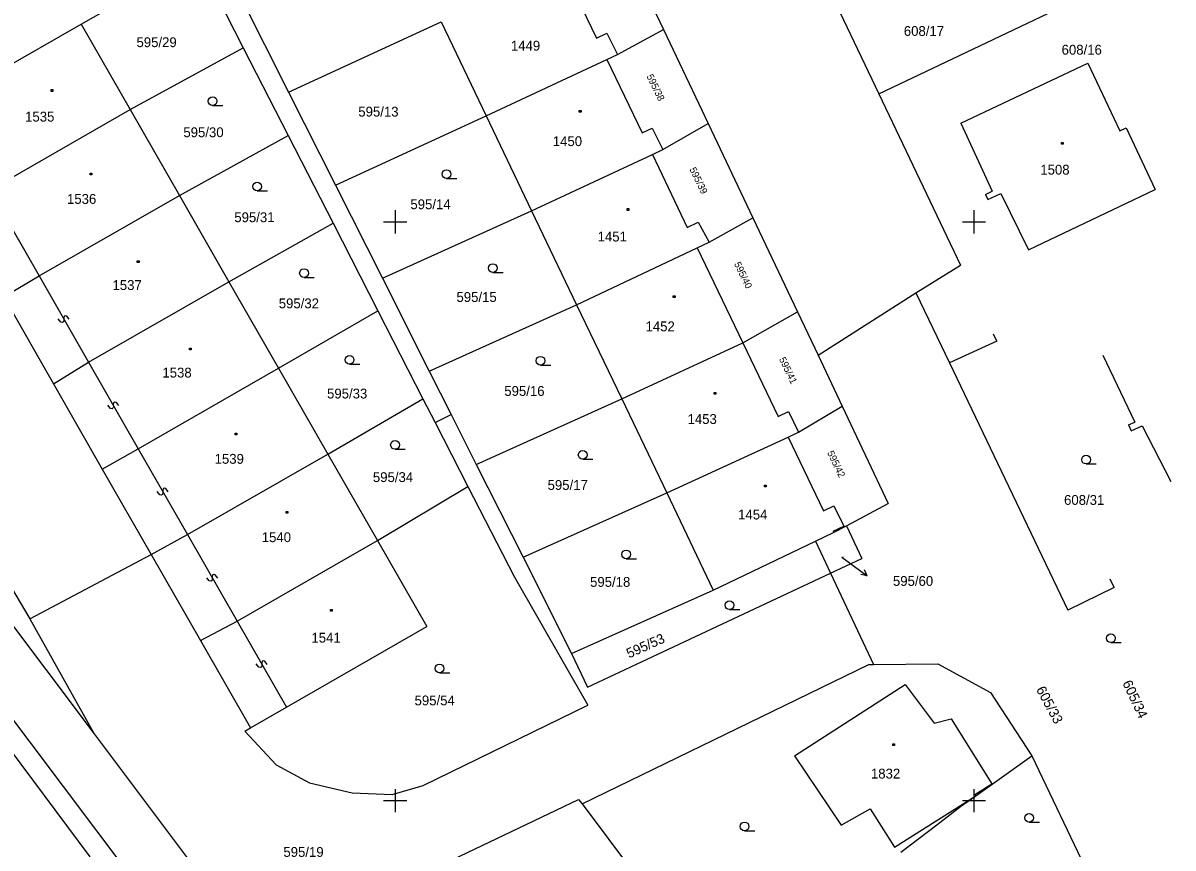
# Model space of a CAD drawing. Extents: x -493648 to -493033, y -1127718 to -1127026.
# Drawn here: x -493132.1 to -493032.8, y -1127404.1 to -1127332.8 of the extents above; entities that cross this region are included whole.
import ezdxf

# ---------------------------------------------------------------- set-up
doc = ezdxf.new("R2010")
doc.units = 0
doc.layers.add('katastrální mapa', color=7, linetype='Continuous')
doc.layers.add('síť', color=7, linetype='Continuous')

msp = doc.modelspace()

# ---------------------------------------------------------------- linework, layer by layer
at = {"layer": 'katastrální mapa'}
for p, q in [((-493068.15, -1127318.07), (-493058.21, -1127338.94)), ((-493080.67, -1127325.26), (-493076.81, -1127333.39)), ((-493127.12, -1127332.93), (-493117.09, -1127327.19)), ((-493117.09, -1127327.19), (-493113.12, -1127334.96)), ((-493085.59, -1127327.9), (-493082.6, -1127334.13)), ((-493058.21, -1127338.94), (-493036.63, -1127328.66)), ((-493113.39, -1127330.48), (-493109.2, -1127338.8)), ((-493139.25, -1127339.87), (-493127.12, -1127332.93)), ((-493127.12, -1127332.93), (-493122.88, -1127340.31)), ((-493109.2, -1127338.8), (-493096.02, -1127332.72)), ((-493096.02, -1127332.72), (-493092.13, -1127340.84)), ((-493080.8, -1127335.56), (-493076.81, -1127333.39)), ((-493076.81, -1127333.39), (-493072.96, -1127341.52)), ((-493082.6, -1127334.13), (-493081.7, -1127333.7)), ((-493081.7, -1127333.7), (-493080.8, -1127335.56)), ((-493122.88, -1127340.31), (-493113.12, -1127334.96)), ((-493113.12, -1127334.96), (-493109.24, -1127342.53)), ((-493092.13, -1127340.84), (-493081.71, -1127335.99)), ((-493081.71, -1127335.99), (-493080.8, -1127335.56)), ((-493081.71, -1127335.99), (-493078.67, -1127342.32)), ((-493051.15, -1127341.49), (-493040.17, -1127336.29)), ((-493040.17, -1127336.29), (-493037.4, -1127342.13)), ((-493159.33, -1127337.18), (-493131.56, -1127384.31)), ((-493129.72, -1127338.58), (-493129.57, -1127338.58)), ((-493129.72, -1127338.73), (-493129.72, -1127338.58)), ((-493129.57, -1127338.73), (-493129.72, -1127338.73)), ((-493129.57, -1127338.58), (-493129.57, -1127338.73)), ((-493109.2, -1127338.8), (-493105.15, -1127346.83)), ((-493058.21, -1127338.94), (-493051.16, -1127353.75)), ((-493135.01, -1127347.27), (-493122.88, -1127340.31)), ((-493122.88, -1127340.31), (-493118.63, -1127347.72)), ((-493115.76, -1127339.95), (-493114.88, -1127339.95)), ((-493084.09, -1127340.38), (-493083.94, -1127340.38)), ((-493084.09, -1127340.53), (-493084.09, -1127340.38)), ((-493083.94, -1127340.38), (-493083.94, -1127340.53)), ((-493105.15, -1127346.83), (-493092.13, -1127340.84)), ((-493092.13, -1127340.84), (-493088.21, -1127349.04)), ((-493083.94, -1127340.53), (-493084.09, -1127340.53)), ((-493173.25, -1127342.08), (-493126.36, -1127404.86)), ((-493078.67, -1127342.32), (-493077.81, -1127341.9)), ((-493077.81, -1127341.9), (-493076.87, -1127343.74)), ((-493076.87, -1127343.74), (-493072.96, -1127341.52)), ((-493072.96, -1127341.52), (-493069.1, -1127349.65)), ((-493051.15, -1127341.49), (-493048.43, -1127347.34)), ((-493037.4, -1127342.13), (-493036.86, -1127341.87)), ((-493036.86, -1127341.87), (-493034.34, -1127347.21)), ((-493118.63, -1127347.72), (-493109.24, -1127342.53)), ((-493109.24, -1127342.53), (-493105.36, -1127350.13)), ((-493042.44, -1127343.14), (-493042.29, -1127343.14)), ((-493042.44, -1127343.29), (-493042.44, -1127343.14)), ((-493042.29, -1127343.29), (-493042.44, -1127343.29)), ((-493042.29, -1127343.14), (-493042.29, -1127343.29)), ((-493088.21, -1127349.04), (-493077.78, -1127344.18)), ((-493077.78, -1127344.18), (-493076.87, -1127343.74)), ((-493077.78, -1127344.18), (-493074.76, -1127350.48)), ((-493126.34, -1127345.8), (-493126.19, -1127345.8)), ((-493126.34, -1127345.95), (-493126.34, -1127345.8)), ((-493126.19, -1127345.95), (-493126.34, -1127345.95)), ((-493126.19, -1127345.8), (-493126.19, -1127345.95)), ((-493095.56, -1127346.25), (-493094.68, -1127346.25)), ((-493135.01, -1127347.27), (-493130.75, -1127354.68)), ((-493111.91, -1127347.32), (-493111.03, -1127347.32)), ((-493105.15, -1127346.83), (-493101.1, -1127354.87)), ((-493049.01, -1127347.63), (-493048.43, -1127347.34)), ((-493045.28, -1127352.43), (-493034.34, -1127347.21)), ((-493130.75, -1127354.68), (-493118.63, -1127347.72)), ((-493118.63, -1127347.72), (-493114.35, -1127355.18)), ((-493049.01, -1127347.63), (-493048.8, -1127348.08)), ((-493048.8, -1127348.08), (-493047.68, -1127347.54)), ((-493047.68, -1127347.54), (-493045.28, -1127352.43)), ((-493101.1, -1127354.87), (-493088.21, -1127349.04)), ((-493088.21, -1127349.04), (-493084.32, -1127357.16)), ((-493079.97, -1127348.86), (-493079.82, -1127348.86)), ((-493079.97, -1127349.01), (-493079.97, -1127348.86)), ((-493079.82, -1127349.01), (-493079.97, -1127349.01)), ((-493079.82, -1127348.86), (-493079.82, -1127349.01)), ((-493114.35, -1127355.18), (-493105.36, -1127350.13)), ((-493105.36, -1127350.13), (-493101.48, -1127357.7)), ((-493074.76, -1127350.48), (-493073.81, -1127350.02)), ((-493073.81, -1127350.02), (-493072.86, -1127351.75)), ((-493072.86, -1127351.75), (-493069.1, -1127349.65)), ((-493069.1, -1127349.65), (-493065.24, -1127357.79)), ((-493084.32, -1127357.16), (-493073.91, -1127352.25)), ((-493073.91, -1127352.25), (-493072.86, -1127351.75)), ((-493073.91, -1127352.25), (-493069.97, -1127360.44)), ((-493122.27, -1127353.36), (-493122.12, -1127353.36)), ((-493122.27, -1127353.51), (-493122.27, -1127353.36)), ((-493122.12, -1127353.51), (-493122.27, -1127353.51)), ((-493122.12, -1127353.36), (-493122.12, -1127353.51)), ((-493055.01, -1127356.13), (-493051.16, -1127353.75)), ((-493133.81, -1127356.48), (-493130.75, -1127354.68)), ((-493130.75, -1127354.68), (-493126.48, -1127362.13)), ((-493126.48, -1127362.13), (-493114.35, -1127355.18)), ((-493114.35, -1127355.18), (-493110.07, -1127362.64)), ((-493107.87, -1127354.8), (-493106.99, -1127354.8)), ((-493101.1, -1127354.87), (-493097.05, -1127362.91)), ((-493091.56, -1127354.37), (-493090.68, -1127354.37)), ((-493063.47, -1127361.52), (-493055.01, -1127356.13)), ((-493055.01, -1127356.13), (-493052.11, -1127362.18)), ((-493160.5, -1127356.56), (-493118.62, -1127412.12)), ((-493133.81, -1127356.48), (-493129.51, -1127363.99)), ((-493097.05, -1127362.91), (-493084.32, -1127357.16)), ((-493084.32, -1127357.16), (-493080.43, -1127365.28)), ((-493075.97, -1127356.38), (-493075.82, -1127356.38)), ((-493075.97, -1127356.53), (-493075.97, -1127356.38)), ((-493075.82, -1127356.53), (-493075.97, -1127356.53)), ((-493075.82, -1127356.38), (-493075.82, -1127356.53)), ((-493128.58, -1127358.16), (-493128.62, -1127358.29)), ((-493128.5, -1127358.11), (-493128.58, -1127358.16)), ((-493128.36, -1127358.14), (-493128.5, -1127358.11)), ((-493128.14, -1127358.42), (-493128.36, -1127358.14)), ((-493110.07, -1127362.64), (-493101.48, -1127357.7)), ((-493101.48, -1127357.7), (-493097.6, -1127365.28)), ((-493069.97, -1127360.44), (-493065.24, -1127357.79)), ((-493065.24, -1127357.79), (-493063.47, -1127361.52)), ((-493128.87, -1127358.67), (-493129.09, -1127358.39)), ((-493128.73, -1127358.7), (-493128.87, -1127358.67)), ((-493128.65, -1127358.65), (-493128.73, -1127358.7)), ((-493128.61, -1127358.52), (-493128.65, -1127358.65)), ((-493128.62, -1127358.29), (-493128.61, -1127358.52)), ((-493048.04, -1127360.3), (-493048.32, -1127359.71)), ((-493150.83, -1127361.25), (-493125.99, -1127394.24)), ((-493117.76, -1127360.92), (-493117.61, -1127360.92)), ((-493117.76, -1127361.07), (-493117.76, -1127360.92)), ((-493117.61, -1127361.07), (-493117.76, -1127361.07)), ((-493117.61, -1127360.92), (-493117.61, -1127361.07)), ((-493080.43, -1127365.28), (-493069.97, -1127360.44)), ((-493069.97, -1127360.44), (-493066.92, -1127366.81)), ((-493048.04, -1127360.3), (-493052.11, -1127362.18)), ((-493129.51, -1127363.99), (-493126.48, -1127362.13)), ((-493126.48, -1127362.13), (-493122.19, -1127369.6)), ((-493063.47, -1127361.52), (-493061.39, -1127365.92)), ((-493052.11, -1127362.18), (-493041.88, -1127383.55)), ((-493038.87, -1127361.52), (-493036.11, -1127367.3)), ((-493122.19, -1127369.6), (-493110.07, -1127362.64)), ((-493110.07, -1127362.64), (-493105.81, -1127370.06)), ((-493103.93, -1127362.29), (-493103.05, -1127362.29)), ((-493097.05, -1127362.91), (-493095.17, -1127366.64)), ((-493087.44, -1127362.37), (-493086.56, -1127362.37)), ((-493129.51, -1127363.99), (-493125.29, -1127371.37)), ((-493072.45, -1127364.75), (-493072.3, -1127364.75)), ((-493072.45, -1127364.9), (-493072.45, -1127364.75)), ((-493072.3, -1127364.9), (-493072.45, -1127364.9)), ((-493072.3, -1127364.75), (-493072.3, -1127364.9)), ((-493124.59, -1127366.13), (-493124.81, -1127365.85)), ((-493124.45, -1127366.16), (-493124.59, -1127366.13)), ((-493124.37, -1127366.11), (-493124.45, -1127366.16)), ((-493124.33, -1127365.98), (-493124.37, -1127366.11)), ((-493124.3, -1127365.62), (-493124.34, -1127365.75)), ((-493124.34, -1127365.75), (-493124.33, -1127365.98)), ((-493124.22, -1127365.57), (-493124.3, -1127365.62)), ((-493124.08, -1127365.6), (-493124.22, -1127365.57)), ((-493123.86, -1127365.88), (-493124.08, -1127365.6)), ((-493105.81, -1127370.06), (-493097.6, -1127365.28)), ((-493097.6, -1127365.28), (-493096.54, -1127367.35)), ((-493093, -1127370.95), (-493080.43, -1127365.28)), ((-493080.43, -1127365.28), (-493076.54, -1127373.4)), ((-493065.16, -1127368.17), (-493061.39, -1127365.92)), ((-493061.39, -1127365.92), (-493057.4, -1127374.32)), ((-493096.54, -1127367.35), (-493095.17, -1127366.64)), ((-493095.17, -1127366.64), (-493093, -1127370.95)), ((-493066.92, -1127366.81), (-493066.03, -1127366.39)), ((-493066.03, -1127366.39), (-493065.16, -1127368.17)), ((-493096.54, -1127367.35), (-493093.72, -1127372.85)), ((-493066.06, -1127368.61), (-493065.16, -1127368.17)), ((-493036.66, -1127367.54), (-493036.11, -1127367.3)), ((-493036.66, -1127367.54), (-493036.41, -1127368.06)), ((-493036.41, -1127368.06), (-493035.48, -1127367.62)), ((-493035.48, -1127367.62), (-493032.99, -1127372.44)), ((-493113.81, -1127368.25), (-493113.66, -1127368.25)), ((-493113.81, -1127368.4), (-493113.81, -1127368.25)), ((-493113.66, -1127368.4), (-493113.81, -1127368.4)), ((-493113.66, -1127368.25), (-493113.66, -1127368.4)), ((-493076.54, -1127373.4), (-493066.06, -1127368.61)), ((-493066.06, -1127368.61), (-493063.01, -1127374.97)), ((-493125.29, -1127371.37), (-493122.19, -1127369.6)), ((-493122.19, -1127369.6), (-493117.94, -1127377.02)), ((-493117.94, -1127377.02), (-493105.81, -1127370.06)), ((-493105.81, -1127370.06), (-493101.52, -1127377.54)), ((-493100.01, -1127369.65), (-493099.13, -1127369.65)), ((-493093, -1127370.95), (-493088.95, -1127378.98)), ((-493083.8, -1127370.5), (-493082.92, -1127370.5)), ((-493040.32, -1127370.92), (-493039.44, -1127370.92)), ((-493125.29, -1127371.37), (-493121.07, -1127378.75)), ((-493120.03, -1127373.06), (-493120.07, -1127373.2)), ((-493119.95, -1127373.01), (-493120.03, -1127373.06)), ((-493119.81, -1127373.05), (-493119.95, -1127373.01)), ((-493119.59, -1127373.33), (-493119.81, -1127373.05)), ((-493101.52, -1127377.54), (-493093.72, -1127372.85)), ((-493093.72, -1127372.85), (-493089.73, -1127380.65)), ((-493068.09, -1127372.75), (-493067.94, -1127372.75)), ((-493068.09, -1127372.9), (-493068.09, -1127372.75)), ((-493067.94, -1127372.9), (-493068.09, -1127372.9)), ((-493067.94, -1127372.75), (-493067.94, -1127372.9)), ((-493120.32, -1127373.57), (-493120.54, -1127373.29)), ((-493120.18, -1127373.61), (-493120.32, -1127373.57)), ((-493120.1, -1127373.56), (-493120.18, -1127373.61)), ((-493120.06, -1127373.42), (-493120.1, -1127373.56)), ((-493120.07, -1127373.2), (-493120.06, -1127373.42)), ((-493088.95, -1127378.98), (-493076.54, -1127373.4)), ((-493076.54, -1127373.4), (-493072.52, -1127381.81)), ((-493109.41, -1127375.02), (-493109.26, -1127375.02)), ((-493109.41, -1127375.17), (-493109.41, -1127375.02)), ((-493109.26, -1127375.17), (-493109.41, -1127375.17)), ((-493109.26, -1127375.02), (-493109.26, -1127375.17)), ((-493063.01, -1127374.97), (-493062.1, -1127374.53)), ((-493062.1, -1127374.53), (-493061.24, -1127376.29)), ((-493061.02, -1127376.25), (-493057.4, -1127374.32)), ((-493121.07, -1127378.75), (-493117.94, -1127377.02)), ((-493117.94, -1127377.02), (-493113.65, -1127384.49)), ((-493063.68, -1127377.58), (-493062.13, -1127376.84)), ((-493062.16, -1127376.73), (-493061.24, -1127376.29)), ((-493062.16, -1127376.73), (-493062.13, -1127376.84)), ((-493062.13, -1127376.84), (-493061.02, -1127376.25)), ((-493061.02, -1127376.25), (-493059.68, -1127379.09)), ((-493113.65, -1127384.49), (-493101.52, -1127377.54)), ((-493101.52, -1127377.54), (-493097.26, -1127384.97)), ((-493072.52, -1127381.81), (-493063.68, -1127377.58)), ((-493063.68, -1127377.58), (-493062.38, -1127380.35)), ((-493131.56, -1127384.31), (-493121.07, -1127378.75)), ((-493121.07, -1127378.75), (-493116.82, -1127386.17)), ((-493088.95, -1127378.98), (-493084.76, -1127387.3)), ((-493080.04, -1127379.1), (-493079.16, -1127379.1)), ((-493062.38, -1127380.35), (-493059.68, -1127379.09)), ((-493061.42, -1127378.97), (-493060.43, -1127379.69)), ((-493060.43, -1127379.69), (-493059.22, -1127380.57)), ((-493059.22, -1127380.57), (-493059.47, -1127380.07)), ((-493116.05, -1127381.02), (-493116.27, -1127380.74)), ((-493115.91, -1127381.05), (-493116.05, -1127381.02)), ((-493115.83, -1127381), (-493115.91, -1127381.05)), ((-493115.79, -1127380.87), (-493115.83, -1127381)), ((-493115.76, -1127380.51), (-493115.8, -1127380.64)), ((-493115.8, -1127380.64), (-493115.79, -1127380.87)), ((-493115.68, -1127380.46), (-493115.76, -1127380.51)), ((-493115.54, -1127380.49), (-493115.68, -1127380.46)), ((-493115.32, -1127380.77), (-493115.54, -1127380.49)), ((-493089.73, -1127380.65), (-493083.36, -1127391.75)), ((-493083.39, -1127390.19), (-493062.38, -1127380.35)), ((-493062.38, -1127380.35), (-493058.68, -1127388.24)), ((-493059.22, -1127380.57), (-493059.77, -1127380.48)), ((-493037.88, -1127381.6), (-493038.23, -1127380.87)), ((-493084.76, -1127387.3), (-493072.52, -1127381.81)), ((-493037.88, -1127381.6), (-493041.88, -1127383.55)), ((-493105.58, -1127383.48), (-493105.43, -1127383.48)), ((-493105.58, -1127383.63), (-493105.58, -1127383.48)), ((-493105.43, -1127383.63), (-493105.58, -1127383.63)), ((-493105.43, -1127383.48), (-493105.43, -1127383.63)), ((-493071.11, -1127383.5), (-493070.23, -1127383.5)), ((-493131.56, -1127384.31), (-493125.99, -1127394.24)), ((-493116.82, -1127386.17), (-493113.65, -1127384.49)), ((-493113.65, -1127384.49), (-493109.38, -1127391.93)), ((-493109.38, -1127391.93), (-493097.26, -1127384.97)), ((-493116.82, -1127386.17), (-493112.5, -1127393.72)), ((-493038.17, -1127386.35), (-493037.29, -1127386.35)), ((-493111.48, -1127387.96), (-493111.52, -1127388.1)), ((-493111.4, -1127387.91), (-493111.48, -1127387.96)), ((-493111.26, -1127387.95), (-493111.4, -1127387.91)), ((-493111.04, -1127388.23), (-493111.26, -1127387.95)), ((-493084.76, -1127387.3), (-493083.39, -1127390.19)), ((-493111.77, -1127388.47), (-493111.99, -1127388.19)), ((-493111.63, -1127388.51), (-493111.77, -1127388.47)), ((-493111.55, -1127388.46), (-493111.63, -1127388.51)), ((-493111.51, -1127388.32), (-493111.55, -1127388.46)), ((-493111.52, -1127388.1), (-493111.51, -1127388.32)), ((-493096.16, -1127388.95), (-493095.28, -1127388.95)), ((-493083.85, -1127400.29), (-493059.07, -1127388.24)), ((-493059.07, -1127388.24), (-493058.68, -1127388.24)), ((-493058.68, -1127388.24), (-493053.13, -1127388.18)), ((-493053.13, -1127388.18), (-493048.57, -1127390.66)), ((-493065.51, -1127396.12), (-493055.93, -1127389.98)), ((-493055.93, -1127389.98), (-493053.45, -1127393.31)), ((-493048.57, -1127390.66), (-493045.01, -1127396.13)), ((-493112.5, -1127393.72), (-493109.38, -1127391.93)), ((-493097.59, -1127398.69), (-493083.36, -1127391.75)), ((-493053.45, -1127393.31), (-493051.96, -1127392.92)), ((-493051.96, -1127392.92), (-493048.46, -1127398.56)), ((-493112.97, -1127393.99), (-493112.5, -1127393.72)), ((-493112.97, -1127393.99), (-493110.27, -1127396.9)), ((-493125.99, -1127394.24), (-493114.4, -1127409.66)), ((-493057.02, -1127395.1), (-493056.87, -1127395.1)), ((-493057.02, -1127395.25), (-493057.02, -1127395.1)), ((-493056.87, -1127395.25), (-493057.02, -1127395.25)), ((-493056.87, -1127395.1), (-493056.87, -1127395.25)), ((-493110.27, -1127396.9), (-493107.39, -1127398.46)), ((-493065.51, -1127396.12), (-493061.47, -1127402.12)), ((-493049.84, -1127399.6), (-493045.01, -1127396.13)), ((-493045.01, -1127396.13), (-493032.81, -1127421.58)), ((-493107.39, -1127398.46), (-493103.7, -1127399.34)), ((-493100.26, -1127399.47), (-493097.59, -1127398.69)), ((-493049.92, -1127399.47), (-493048.46, -1127398.56)), ((-493103.7, -1127399.34), (-493100.26, -1127399.47)), ((-493100.83, -1127407.84), (-493084.15, -1127399.89)), ((-493084.15, -1127399.89), (-493083.85, -1127400.29)), ((-493056.86, -1127404.02), (-493049.84, -1127399.6)), ((-493051.16, -1127400.5), (-493049.84, -1127399.6)), ((-493049.92, -1127399.47), (-493049.84, -1127399.6)), ((-493083.85, -1127400.29), (-493071.84, -1127416.28)), ((-493061.47, -1127402.12), (-493058.97, -1127400.72)), ((-493058.97, -1127400.72), (-493056.86, -1127404.02)), ((-493053.22, -1127402.08), (-493051.16, -1127400.5)), ((-493045.23, -1127401.86), (-493044.35, -1127401.86)), ((-493069.81, -1127402.6), (-493068.93, -1127402.6)), ((-493056.32, -1127404.44), (-493053.22, -1127402.08))]:
    msp.add_line(p, q, dxfattribs=at)
for centre in [(-493115.76, -1127339.575), (-493095.56, -1127345.875), (-493111.91, -1127346.945), (-493107.87, -1127354.425), (-493091.56, -1127353.995), (-493103.93, -1127361.915), (-493087.44, -1127361.995), (-493100.01, -1127369.275), (-493083.8, -1127370.125), (-493040.32, -1127370.545), (-493080.04, -1127378.725), (-493071.11, -1127383.125), (-493038.17, -1127385.975), (-493096.16, -1127388.575), (-493069.81, -1127402.225), (-493045.23, -1127401.485)]:
    msp.add_circle(centre, 0.375, dxfattribs=at)
at = {"layer": 'síť'}
for p, q in [((-493100, -1127349), (-493100, -1127351)), ((-493050, -1127349), (-493050, -1127351)), ((-493101, -1127350), (-493099, -1127350)), ((-493051, -1127350), (-493049, -1127350)), ((-493100, -1127399), (-493100, -1127401)), ((-493050, -1127399), (-493050, -1127401)), ((-493101, -1127400), (-493099, -1127400)), ((-493051, -1127400), (-493049, -1127400))]:
    msp.add_line(p, q, dxfattribs=at)

# ---------------------------------------------------------------- texts
at = {"layer": 'katastrální mapa'}
for s, height, p in [('608/17', 0.849996, (-493056.06, -1127333.94)), ('595/29', 0.849996, (-493122.34, -1127334.91)), ('1449', 0.849996, (-493090, -1127335.21)), ('608/16', 0.849996, (-493042.43, -1127335.56)), ('595/13', 0.849996, (-493103.18, -1127340.91)), ('1535', 0.849996, (-493131.96, -1127341.34)), ('595/30', 0.849996, (-493118.29, -1127342.69)), ('1450', 0.849996, (-493086.38, -1127343.46)), ('1508', 0.849996, (-493044.27, -1127345.92)), ('1536', 0.849996, (-493128.34, -1127348.45)), ('595/14', 0.849996, (-493098.68, -1127348.91)), ('595/31', 0.849996, (-493113.89, -1127350.03)), ('1451', 0.849996, (-493082.51, -1127351.7)), ('1537', 0.849996, (-493124.41, -1127355.89)), ('595/15', 0.849996, (-493094.7, -1127356.92)), ('595/32', 0.849996, (-493110.05, -1127357.47)), ('1452', 0.849996, (-493078.37, -1127359.46)), ('1538', 0.849996, (-493120.1, -1127363.45)), ('595/16', 0.849996, (-493090.57, -1127365.04)), ('595/33', 0.849996, (-493105.88, -1127365.26)), ('1453', 0.849996, (-493074.74, -1127367.46)), ('1539', 0.849996, (-493115.59, -1127370.9)), ('595/34', 0.849996, (-493101.92, -1127372.48)), ('595/17', 0.849996, (-493086.83, -1127373.16)), ('608/31', 0.849996, (-493042.22, -1127374.45)), ('1454', 0.849996, (-493070.37, -1127375.71)), ('1540', 0.849996, (-493111.52, -1127377.67)), ('595/60', 0.049998, (-493061.42, -1127378.97)), ('595/18', 0.849996, (-493083.16, -1127381.53)), ('595/60', 0.849996, (-493057, -1127381.45)), ('1541', 0.849996, (-493107.23, -1127386.35)), ('595/54', 0.849996, (-493098.32, -1127391.77)), ('1832', 0.849996, (-493058.9, -1127398.09)), ('595/19', 0.849996, (-493109.65, -1127404.86))]:
    msp.add_text(s, height=height, dxfattribs=at).set_placement(p)
for s, height, rotation, p in [('595/38', 0.599994, 295.875, (-493078.3, -1127337.42)), ('595/39', 0.599994, 295.875, (-493074.59, -1127345.46)), ('595/40', 0.599994, 295.875, (-493070.74, -1127353.63)), ('595/41', 0.599994, 295.875, (-493066.86, -1127361.86)), ('595/42', 0.599994, 295.875, (-493062.7, -1127369.95)), ('595/53', 0.849996, 24.183, (-493079.79, -1127387.72)), ('605/34', 0.849996, 295.074, (-493037.2, -1127389.84)), ('605/33', 0.849996, 298.341, (-493044.66, -1127390.4))]:
    msp.add_text(s, height=height, rotation=rotation, dxfattribs=at).set_placement(p)

doc.saveas('drawing.dxf')
